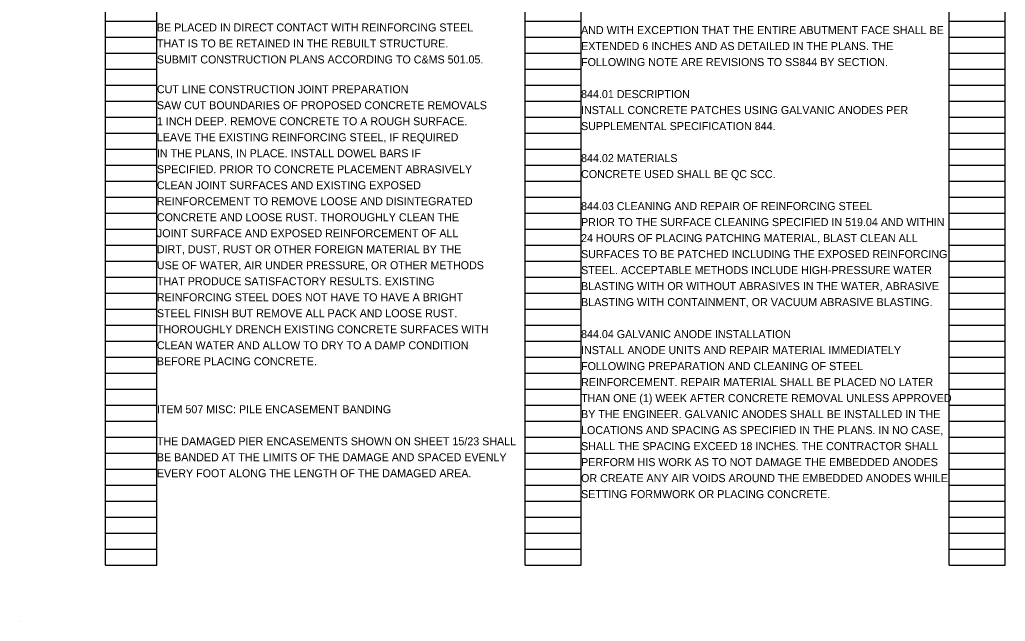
# Model space of a CAD drawing. Extents: x 0 to 66.4, y 0 to 28.8.
# Drawn here: x 34.41 to 51.65, y 0 to 10.53 of the extents above; entities that cross this region are included whole.
import ezdxf

# ---------------------------------------------------------------- set-up
doc = ezdxf.new("R2010")
doc.units = 0
doc.layers.add('SH_Data', color=7, linetype='Continuous')
doc.layers.add('SH_Text', color=7, linetype='Continuous')

msp = doc.modelspace()

# ---------------------------------------------------------------- linework, layer by layer
at = {"layer": 'SH_Data'}
for p, q in [((35.914, 0.98), (35.914, 21.14)), ((35.914, 0.98), (35.914, 21.14)), ((36.814, 0.98), (36.814, 21.14)), ((36.814, 0.98), (36.814, 21.14)), ((43.254, 0.98), (43.254, 21.14)), ((43.254, 0.98), (43.254, 21.14)), ((44.234, 0.98), (44.234, 21.14)), ((44.234, 0.98), (44.234, 21.14)), ((50.674, 0.98), (50.674, 21.14)), ((50.674, 0.98), (50.674, 21.14)), ((51.654, 0.98), (51.654, 21.14)), ((51.654, 0.98), (51.654, 21.14)), ((35.914, 10.5), (36.814, 10.5)), ((35.914, 10.5), (36.814, 10.5)), ((43.254, 10.5), (44.234, 10.5)), ((43.254, 10.5), (44.234, 10.5)), ((50.674, 10.5), (51.654, 10.5)), ((50.674, 10.5), (51.654, 10.5)), ((35.914, 10.22), (36.814, 10.22)), ((35.914, 10.22), (36.814, 10.22)), ((43.254, 10.22), (44.234, 10.22)), ((43.254, 10.22), (44.234, 10.22)), ((50.674, 10.22), (51.654, 10.22)), ((50.674, 10.22), (51.654, 10.22)), ((35.914, 9.94), (36.814, 9.94)), ((35.914, 9.94), (36.814, 9.94)), ((43.254, 9.94), (44.234, 9.94)), ((43.254, 9.94), (44.234, 9.94)), ((50.674, 9.94), (51.654, 9.94)), ((50.674, 9.94), (51.654, 9.94)), ((35.914, 9.66), (36.814, 9.66)), ((35.914, 9.66), (36.814, 9.66)), ((43.254, 9.66), (44.234, 9.66)), ((43.254, 9.66), (44.234, 9.66)), ((50.674, 9.66), (51.654, 9.66)), ((50.674, 9.66), (51.654, 9.66)), ((35.914, 9.38), (36.814, 9.38)), ((35.914, 9.38), (36.814, 9.38)), ((43.254, 9.38), (44.234, 9.38)), ((43.254, 9.38), (44.234, 9.38)), ((50.674, 9.38), (51.654, 9.38)), ((50.674, 9.38), (51.654, 9.38)), ((35.914, 9.1), (36.814, 9.1)), ((35.914, 9.1), (36.814, 9.1)), ((43.254, 9.1), (44.234, 9.1)), ((43.254, 9.1), (44.234, 9.1)), ((50.674, 9.1), (51.654, 9.1)), ((50.674, 9.1), (51.654, 9.1)), ((35.914, 8.82), (36.814, 8.82)), ((35.914, 8.82), (36.814, 8.82)), ((43.254, 8.82), (44.234, 8.82)), ((43.254, 8.82), (44.234, 8.82)), ((50.674, 8.82), (51.654, 8.82)), ((50.674, 8.82), (51.654, 8.82)), ((35.914, 8.54), (36.814, 8.54)), ((35.914, 8.54), (36.814, 8.54)), ((43.254, 8.54), (44.234, 8.54)), ((43.254, 8.54), (44.234, 8.54)), ((50.674, 8.54), (51.654, 8.54)), ((50.674, 8.54), (51.654, 8.54)), ((35.914, 8.26), (36.814, 8.26)), ((35.914, 8.26), (36.814, 8.26)), ((43.254, 8.26), (44.234, 8.26)), ((43.254, 8.26), (44.234, 8.26)), ((50.674, 8.26), (51.654, 8.26)), ((50.674, 8.26), (51.654, 8.26)), ((35.914, 7.98), (36.814, 7.98)), ((35.914, 7.98), (36.814, 7.98)), ((43.254, 7.98), (44.234, 7.98)), ((43.254, 7.98), (44.234, 7.98)), ((50.674, 7.98), (51.654, 7.98)), ((50.674, 7.98), (51.654, 7.98)), ((35.914, 7.7), (36.814, 7.7)), ((35.914, 7.7), (36.814, 7.7)), ((43.254, 7.7), (44.234, 7.7)), ((43.254, 7.7), (44.234, 7.7)), ((50.674, 7.7), (51.654, 7.7)), ((50.674, 7.7), (51.654, 7.7)), ((35.914, 7.42), (36.814, 7.42)), ((35.914, 7.42), (36.814, 7.42)), ((43.254, 7.42), (44.234, 7.42)), ((43.254, 7.42), (44.234, 7.42)), ((50.674, 7.42), (51.654, 7.42)), ((50.674, 7.42), (51.654, 7.42)), ((35.914, 7.14), (36.814, 7.14)), ((35.914, 7.14), (36.814, 7.14)), ((43.254, 7.14), (44.234, 7.14)), ((43.254, 7.14), (44.234, 7.14)), ((50.674, 7.14), (51.654, 7.14)), ((50.674, 7.14), (51.654, 7.14)), ((35.914, 6.86), (36.814, 6.86)), ((35.914, 6.86), (36.814, 6.86)), ((43.254, 6.86), (44.234, 6.86)), ((43.254, 6.86), (44.234, 6.86)), ((50.674, 6.86), (51.654, 6.86)), ((50.674, 6.86), (51.654, 6.86)), ((35.914, 6.58), (36.814, 6.58)), ((35.914, 6.58), (36.814, 6.58)), ((43.254, 6.58), (44.234, 6.58)), ((43.254, 6.58), (44.234, 6.58)), ((50.674, 6.58), (51.654, 6.58)), ((50.674, 6.58), (51.654, 6.58)), ((35.914, 6.3), (36.814, 6.3)), ((35.914, 6.3), (36.814, 6.3)), ((43.254, 6.3), (44.234, 6.3)), ((43.254, 6.3), (44.234, 6.3)), ((50.674, 6.3), (51.654, 6.3)), ((50.674, 6.3), (51.654, 6.3)), ((35.914, 6.02), (36.814, 6.02)), ((35.914, 6.02), (36.814, 6.02)), ((43.254, 6.02), (44.234, 6.02)), ((43.254, 6.02), (44.234, 6.02)), ((50.674, 6.02), (51.654, 6.02)), ((50.674, 6.02), (51.654, 6.02)), ((35.914, 5.74), (36.814, 5.74)), ((35.914, 5.74), (36.814, 5.74)), ((43.254, 5.74), (44.234, 5.74)), ((43.254, 5.74), (44.234, 5.74)), ((50.674, 5.74), (51.654, 5.74)), ((50.674, 5.74), (51.654, 5.74)), ((35.914, 5.46), (36.814, 5.46)), ((35.914, 5.46), (36.814, 5.46)), ((43.254, 5.46), (44.234, 5.46)), ((43.254, 5.46), (44.234, 5.46)), ((50.674, 5.46), (51.654, 5.46)), ((50.674, 5.46), (51.654, 5.46)), ((35.914, 5.18), (36.814, 5.18)), ((35.914, 5.18), (36.814, 5.18)), ((43.254, 5.18), (44.234, 5.18)), ((43.254, 5.18), (44.234, 5.18)), ((50.674, 5.18), (51.654, 5.18)), ((50.674, 5.18), (51.654, 5.18)), ((35.914, 4.9), (36.814, 4.9)), ((35.914, 4.9), (36.814, 4.9)), ((43.254, 4.9), (44.234, 4.9)), ((43.254, 4.9), (44.234, 4.9)), ((50.674, 4.9), (51.654, 4.9)), ((50.674, 4.9), (51.654, 4.9)), ((35.914, 4.62), (36.814, 4.62)), ((35.914, 4.62), (36.814, 4.62)), ((43.254, 4.62), (44.234, 4.62)), ((43.254, 4.62), (44.234, 4.62)), ((50.674, 4.62), (51.654, 4.62)), ((50.674, 4.62), (51.654, 4.62)), ((35.914, 4.34), (36.814, 4.34)), ((35.914, 4.34), (36.814, 4.34)), ((43.254, 4.34), (44.234, 4.34)), ((43.254, 4.34), (44.234, 4.34)), ((50.674, 4.34), (51.654, 4.34)), ((50.674, 4.34), (51.654, 4.34)), ((35.914, 4.06), (36.814, 4.06)), ((35.914, 4.06), (36.814, 4.06)), ((43.254, 4.06), (44.234, 4.06)), ((43.254, 4.06), (44.234, 4.06)), ((50.674, 4.06), (51.654, 4.06)), ((50.674, 4.06), (51.654, 4.06)), ((35.914, 3.78), (36.814, 3.78)), ((35.914, 3.78), (36.814, 3.78)), ((43.254, 3.78), (44.234, 3.78)), ((43.254, 3.78), (44.234, 3.78)), ((50.674, 3.78), (51.654, 3.78)), ((50.674, 3.78), (51.654, 3.78)), ((35.914, 3.5), (36.814, 3.5)), ((35.914, 3.5), (36.814, 3.5)), ((43.254, 3.5), (44.234, 3.5)), ((43.254, 3.5), (44.234, 3.5)), ((50.674, 3.5), (51.654, 3.5)), ((50.674, 3.5), (51.654, 3.5)), ((35.914, 3.22), (36.814, 3.22)), ((35.914, 3.22), (36.814, 3.22)), ((43.254, 3.22), (44.234, 3.22)), ((43.254, 3.22), (44.234, 3.22)), ((50.674, 3.22), (51.654, 3.22)), ((50.674, 3.22), (51.654, 3.22)), ((35.914, 2.94), (36.814, 2.94)), ((35.914, 2.94), (36.814, 2.94)), ((43.254, 2.94), (44.234, 2.94)), ((43.254, 2.94), (44.234, 2.94)), ((50.674, 2.94), (51.654, 2.94)), ((50.674, 2.94), (51.654, 2.94)), ((35.914, 2.66), (36.814, 2.66)), ((35.914, 2.66), (36.814, 2.66)), ((43.254, 2.66), (44.234, 2.66)), ((43.254, 2.66), (44.234, 2.66)), ((50.674, 2.66), (51.654, 2.66)), ((50.674, 2.66), (51.654, 2.66)), ((35.914, 2.38), (36.814, 2.38)), ((35.914, 2.38), (36.814, 2.38)), ((43.254, 2.38), (44.234, 2.38)), ((43.254, 2.38), (44.234, 2.38)), ((50.674, 2.38), (51.654, 2.38)), ((50.674, 2.38), (51.654, 2.38)), ((35.914, 2.1), (36.814, 2.1)), ((35.914, 2.1), (36.814, 2.1)), ((43.254, 2.1), (44.234, 2.1)), ((43.254, 2.1), (44.234, 2.1)), ((50.674, 2.1), (51.654, 2.1)), ((50.674, 2.1), (51.654, 2.1)), ((35.914, 1.82), (36.814, 1.82)), ((35.914, 1.82), (36.814, 1.82)), ((43.254, 1.82), (44.234, 1.82)), ((43.254, 1.82), (44.234, 1.82)), ((50.674, 1.82), (51.654, 1.82)), ((50.674, 1.82), (51.654, 1.82)), ((35.914, 1.54), (36.814, 1.54)), ((35.914, 1.54), (36.814, 1.54)), ((43.254, 1.54), (44.234, 1.54)), ((43.254, 1.54), (44.234, 1.54)), ((50.674, 1.54), (51.654, 1.54)), ((50.674, 1.54), (51.654, 1.54)), ((35.914, 1.26), (36.814, 1.26)), ((35.914, 1.26), (36.814, 1.26)), ((43.254, 1.26), (44.234, 1.26)), ((43.254, 1.26), (44.234, 1.26)), ((50.674, 1.26), (51.654, 1.26)), ((50.674, 1.26), (51.654, 1.26)), ((35.914, 0.98), (36.814, 0.98)), ((35.914, 0.98), (36.814, 0.98)), ((43.254, 0.98), (44.234, 0.98)), ((43.254, 0.98), (44.234, 0.98)), ((50.674, 0.98), (51.654, 0.98)), ((50.674, 0.98), (51.654, 0.98)), ((34.414, 0), (34.414, 0)), ((34.414, 0), (34.414, 0))]:
    msp.add_line(p, q, dxfattribs=at)

# ---------------------------------------------------------------- texts
at = {"layer": 'SH_Text'}
for s, p in [('BE PLACED IN DIRECT CONTACT WITH REINFORCING STEEL', (36.814, 10.321)), ('AND WITH EXCEPTION THAT THE ENTIRE ABUTMENT FACE SHALL BE', (44.234, 10.275)), ('THAT IS TO BE RETAINED IN THE REBUILT STRUCTURE.', (36.814, 10.041)), ('EXTENDED 6 INCHES AND AS DETAILED IN THE PLANS. THE', (44.234, 9.995)), ('SUBMIT CONSTRUCTION PLANS ACCORDING TO C&MS 501.05.', (36.814, 9.761)), ('FOLLOWING NOTE ARE REVISIONS TO SS844 BY SECTION.', (44.234, 9.715)), ('CUT LINE CONSTRUCTION JOINT PREPARATION', (36.814, 9.24)), ('844.01 DESCRIPTION', (44.234, 9.155)), ('SAW CUT BOUNDARIES OF PROPOSED CONCRETE REMOVALS', (36.814, 8.96)), ('INSTALL CONCRETE PATCHES USING GALVANIC ANODES PER', (44.234, 8.875)), ('1 INCH DEEP. REMOVE CONCRETE TO A ROUGH SURFACE.', (36.814, 8.68)), ('SUPPLEMENTAL SPECIFICATION 844.', (44.234, 8.595)), ('LEAVE THE EXISTING REINFORCING STEEL, IF REQUIRED', (36.814, 8.4)), ('IN THE PLANS, IN PLACE. INSTALL DOWEL BARS IF', (36.814, 8.12)), ('844.02 MATERIALS', (44.234, 8.035)), ('SPECIFIED. PRIOR TO CONCRETE PLACEMENT ABRASIVELY', (36.814, 7.84)), ('CONCRETE USED SHALL BE QC SCC.', (44.234, 7.755)), ('CLEAN JOINT SURFACES AND EXISTING EXPOSED', (36.814, 7.56)), ('REINFORCEMENT TO REMOVE LOOSE AND DISINTEGRATED', (36.814, 7.28)), ('844.03 CLEANING AND REPAIR OF REINFORCING STEEL', (44.234, 7.195)), ('CONCRETE AND LOOSE RUST. THOROUGHLY CLEAN THE', (36.814, 7)), ('PRIOR TO THE SURFACE CLEANING SPECIFIED IN 519.04 AND WITHIN', (44.234, 6.915)), ('JOINT SURFACE AND EXPOSED REINFORCEMENT OF ALL', (36.814, 6.72)), ('24 HOURS OF PLACING PATCHING MATERIAL, BLAST CLEAN ALL', (44.234, 6.635)), ('DIRT, DUST, RUST OR OTHER FOREIGN MATERIAL BY THE', (36.814, 6.44)), ('SURFACES TO BE PATCHED INCLUDING THE EXPOSED REINFORCING', (44.234, 6.355)), ('USE OF WATER, AIR UNDER PRESSURE, OR OTHER METHODS', (36.814, 6.16)), ('STEEL. ACCEPTABLE METHODS INCLUDE HIGH-PRESSURE WATER', (44.234, 6.075)), ('THAT PRODUCE SATISFACTORY RESULTS. EXISTING', (36.814, 5.88)), ('BLASTING WITH OR WITHOUT ABRASIVES IN THE WATER, ABRASIVE', (44.234, 5.795)), ('REINFORCING STEEL DOES NOT HAVE TO HAVE A BRIGHT', (36.814, 5.6)), ('BLASTING WITH CONTAINMENT, OR VACUUM ABRASIVE BLASTING.', (44.234, 5.515)), ('STEEL FINISH BUT REMOVE ALL PACK AND LOOSE RUST.', (36.814, 5.32)), ('THOROUGHLY DRENCH EXISTING CONCRETE SURFACES WITH', (36.814, 5.04)), ('844.04 GALVANIC ANODE INSTALLATION', (44.234, 4.955)), ('CLEAN WATER AND ALLOW TO DRY TO A DAMP CONDITION', (36.814, 4.76)), ('INSTALL ANODE UNITS AND REPAIR MATERIAL IMMEDIATELY', (44.234, 4.675)), ('BEFORE PLACING CONCRETE.', (36.814, 4.48)), ('FOLLOWING PREPARATION AND CLEANING OF STEEL', (44.234, 4.395)), ('REINFORCEMENT. REPAIR MATERIAL SHALL BE PLACED NO LATER', (44.234, 4.115)), ('THAN ONE (1) WEEK AFTER CONCRETE REMOVAL UNLESS APPROVED', (44.234, 3.835)), ('ITEM 507 MISC: PILE ENCASEMENT BANDING', (36.814, 3.64)), ('BY THE ENGINEER. GALVANIC ANODES SHALL BE INSTALLED IN THE', (44.234, 3.555)), ('LOCATIONS AND SPACING AS SPECIFIED IN THE PLANS. IN NO CASE,', (44.234, 3.275)), ('THE DAMAGED PIER ENCASEMENTS SHOWN ON SHEET 15/23 SHALL ', (36.814, 3.08)), ('SHALL THE SPACING EXCEED 18 INCHES. THE CONTRACTOR SHALL', (44.234, 2.995)), ('BE BANDED AT THE LIMITS OF THE DAMAGE AND SPACED EVENLY ', (36.814, 2.8)), ('PERFORM HIS WORK AS TO NOT DAMAGE THE EMBEDDED ANODES', (44.234, 2.715)), ('EVERY FOOT ALONG THE LENGTH OF THE DAMAGED AREA.', (36.814, 2.52)), ('OR CREATE ANY AIR VOIDS AROUND THE EMBEDDED ANODES WHILE', (44.234, 2.435)), ('SETTING FORMWORK OR PLACING CONCRETE.', (44.234, 2.155))]:
    msp.add_text(s, height=0.14, dxfattribs=at).set_placement(p)

doc.saveas('drawing.dxf')
